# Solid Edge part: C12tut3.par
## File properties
Author: CADCIM
Template: ansi part.par
Last saved by: Cadcim
Revision: 2
Application: Solid Edge
Accuracy: 0.990
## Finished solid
Body 1: solid body, 11 faces, 16 edges, 6 vertices.
  Faces by surface: plane 7, cylinder 4
  Edges by curve: circle 8, line 7, ellipse 1
Bounding box of the edges (mm): 31.750 x 83.001 x 31.750, from (-15.875, -83.0008, -15.875) to (15.875, 0, 15.875).
Cylindrical faces by radius (mm): R5.5944 x1, R6.35 x1, R7.9375 x1, R15.875 x1
Planar faces by outward normal: +x 1, +y 1, -x 1, -y 3, oblique 1
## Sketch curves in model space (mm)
line (-22.4237, -5.3349, 12.616) -> (-22.3476, -10.0218, 7.7796)
line (-22.2925, -83.0008, 4.287) -> (-22.2949, -73.477, 4.437)
line (-22.1163, -82.8245, -6.899) -> (-22.1187, -73.3007, -6.749)
line (-22.2015, -94.5503, -1.4893) -> (-22.2276, 10.4132, 0.164)
line (-22.3068, -73.4889, 5.1924) -> (-22.3044, -83.0127, 5.0424)
line (-22.3044, -83.0127, 5.0424) -> (-22.1044, -82.8126, -7.6544)
line (-22.1068, -73.2888, -7.5044) -> (-22.1044, -82.8126, -7.6544)
line (-22.0987, -5.0098, -8.0164) -> (-22.0818, -73.2638, -9.0915)
line (-22.3487, -5.2598, 7.8546) -> (-22.3318, -73.5139, 6.7795)
line (-22.3318, -73.5139, 6.7795) -> (-22.0818, -73.2638, -9.0915)
line (-22.4738, -5.3849, 15.7902) -> (-21.9737, -4.8848, -15.9519)
line (-22.4749, -0.623, 15.8652) -> (-22.4738, -5.3849, 15.7902)
line (-22.4749, -0.623, 15.8652) -> (-21.9749, -0.1228, -15.8769)
line (-21.9749, -0.1228, -15.8769) -> (-21.9737, -4.8848, -15.9519)
line (22.225, 0, 0) -> (-22.225, 0, 0)
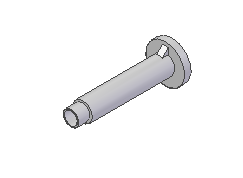
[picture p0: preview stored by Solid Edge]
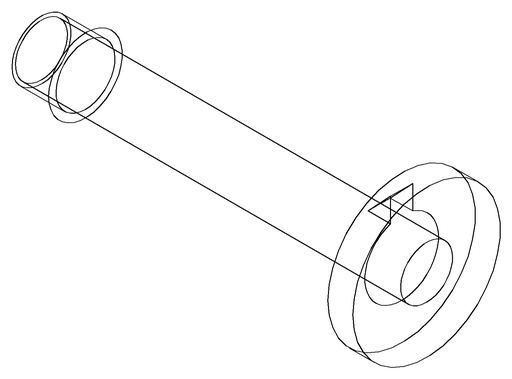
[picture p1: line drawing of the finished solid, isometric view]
